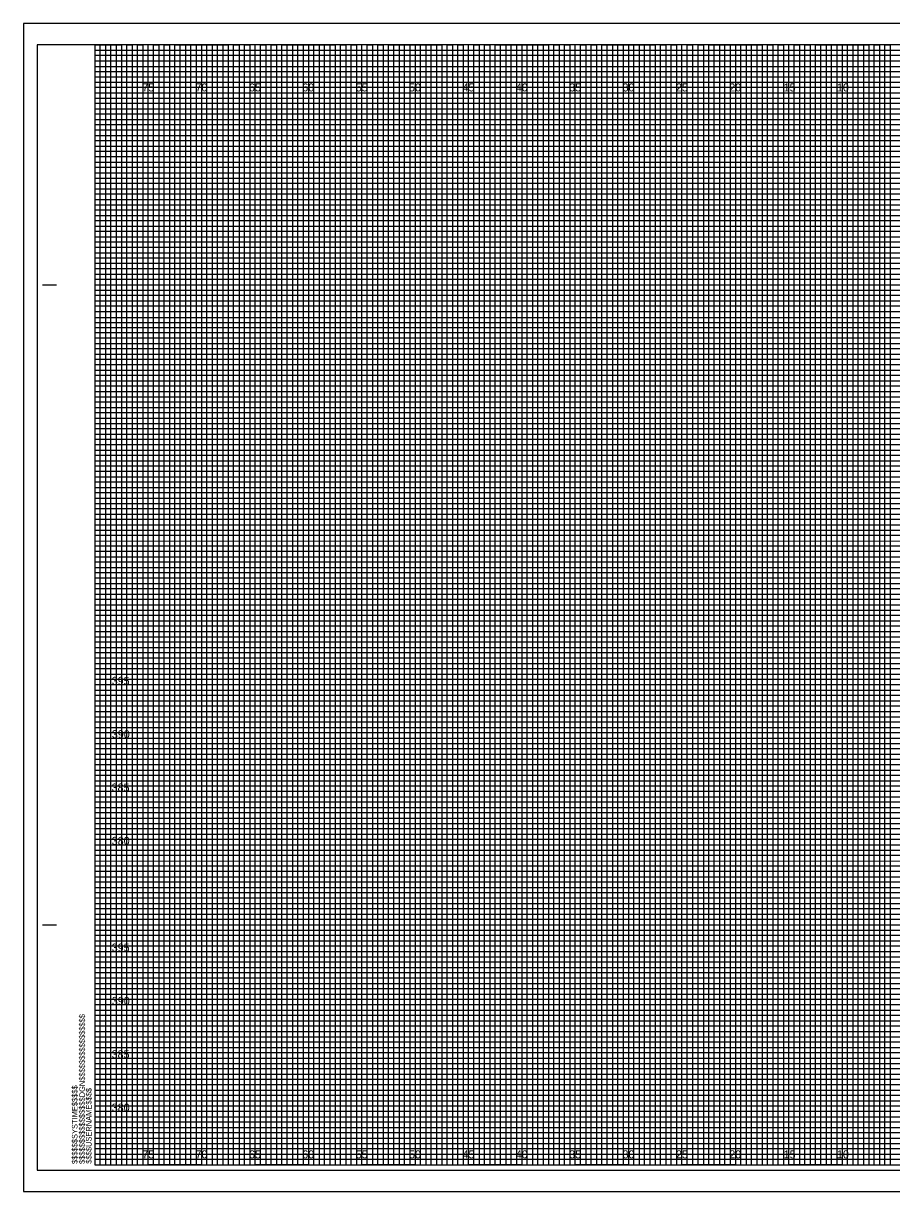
# Model space of a CAD drawing. Extents: x -7 to 162, y -2 to 217.
# Drawn here: x -6.7 to 74.6, y 107.5 to 217 of the extents above; entities that cross this region are included whole.
import ezdxf

# ---------------------------------------------------------------- set-up
doc = ezdxf.new("R2010")
doc.units = 0
for name, color, linetype in [('Exist Cross Section Cell', 7, 'Continuous'), ('Prop CMT Pvmt Course 2', 7, 'Continuous'), ('Prop CMT Pvmt Course 3', 7, 'Continuous'), ('Prop CMT Pvmt Surface Shoulder', 7, 'Continuous'), ('Prop CMT Shld Paved Course 1', 7, 'Continuous'), ('Prop CMT Shld Paved Course 2', 7, 'Continuous'), ('Prop CMT Shld Paved Course 3', 7, 'Continuous'), ('Prop CMT Subgrade Earthwork', 7, 'Continuous'), ('Scratch_Level_3', 7, 'Continuous')]:
    doc.layers.add(name, color=color, linetype=linetype)

msp = doc.modelspace()

# ---------------------------------------------------------------- linework, layer by layer
at = {"layer": 'Prop CMT Pvmt Course 2'}
for p, q in [((0, 214.5), (110.95, 214.5)), ((110.95, 213.99), (0, 213.99)), ((0, 213.99), (0, 213.5)), ((0, 213.5), (110.95, 213.5)), ((110.95, 212.94), (0, 212.94)), ((0, 212.94), (0, 212)), ((0, 212), (160, 212))]:
    msp.add_line(p, q, dxfattribs=at)
for points in [[(0, 211.5), (135, 211.5), (160, 211.5)], [(160, 211), (0, 211)], [(0, 210.5), (160, 210.5)], [(160, 209.5), (0, 209.5)], [(0, 209), (160, 209)], [(160, 208.5), (0, 208.49)], [(0, 208), (160, 208)], [(160, 207), (0, 207)], [(0, 206.5), (160, 206.5), (160, 206), (0, 206)], [(0, 205.5), (160, 205.5), (160, 204.5), (0, 204.5)], [(0, 204), (160, 204), (160, 203.5), (0, 203.5)], [(0, 203), (160, 203), (160, 202), (0, 202)], [(0, 201.5), (160, 201.5), (160, 201), (0, 201)], [(0, 200.5), (160, 200.5), (160, 199.5), (0, 199.5)], [(0, 199), (160, 199), (160, 198.5), (0, 198.5)], [(0, 198), (160, 198), (160, 196.97), (160, 196.5), (160, 196), (0, 196)], [(0, 197), (160, 197), (160, 196.5), (0, 196.5)], [(0, 195.5), (160, 195.5), (160, 194.5), (0, 194.51)], [(0, 194.51), (160, 194.5), (160, 194), (0, 194)], [(0, 193.5), (160, 193.5), (160, 193), (0, 193)], [(0, 192), (160, 192), (160, 191.5), (0, 191.5)], [(0, 191), (160, 191), (160, 190.5), (0, 190.5)], [(-0.04, 189.44), (160, 189.44), (160, 188.94), (-0.04, 188.94)], [(0, 188.5), (160, 188.5), (160, 188), (0, 188)], [(0, 187), (160, 187), (160, 186.5), (0, 186.5)], [(0, 186), (160, 186), (160, 185.5), (0, 185.5)], [(0, 184.5), (160, 184.5), (160, 184), (0, 184)], [(0, 183.5), (160, 183.5), (160, 183), (0, 183)], [(0, 182), (160, 182), (160, 181.5), (0, 181.5)], [(0, 181), (160, 181), (160, 180.5), (0, 180.5)], [(0, 179.5), (160, 179.5), (159.99, 178.99), (0, 179)], [(0, 178.5), (160, 178.5), (160, 178), (0, 178)], [(0, 177), (160, 177), (160, 176.5), (0, 176.5)], [(0, 176), (160, 176), (160, 175.5), (0, 175.5)], [(0, 174.5), (160, 174.5), (160, 174), (0, 174)], [(0, 173.5), (160, 173.5), (160, 173), (0, 173)], [(0, 172), (160, 172), (160, 171.5), (0, 171.5)], [(0, 171), (160, 171), (160, 170.5), (0, 170.5)], [(0, 169.5), (160, 169.5), (160, 169), (0, 169)], [(0, 168.5), (160.03, 168.45), (160, 168), (0, 168)], [(0, 167), (160, 167), (160, 166.5), (0, 166.5)], [(0, 166), (160, 166), (160, 165.5), (0, 165.5)], [(0, 164.5), (160, 164.5), (160, 164), (0, 164)], [(0, 163.5), (160, 163.5), (160, 163), (0, 163)], [(0, 162), (160, 162), (160, 161.5), (0, 161.5)], [(0, 161), (160, 161), (160, 160.5), (0, 160.5)], [(0, 159.5), (160, 159.5), (160, 159), (0, 159)], [(0, 158.5), (160, 158.5), (160, 158), (0, 158)], [(0, 157), (160, 157), (160, 156.5), (0, 156.5)], [(0, 156), (160, 156), (160, 155.5), (0, 155.5)], [(0, 154.5), (160, 154.5), (160, 154), (0, 154)], [(0, 153.5), (160, 153.5), (160, 153), (0, 153)], [(0, 152), (160, 152), (160, 151.5), (0, 151.5)], [(0, 151), (160, 151), (160, 150.5), (0, 150.5)], [(0, 149.5), (160, 149.5), (159.99, 148.99), (0, 149)], [(0, 148.5), (160, 148.5), (160, 148), (0, 148)], [(0, 147), (160, 147), (160, 146.5), (0, 146.5)], [(0, 146), (160, 146), (160, 145.5), (0, 145.5)], [(0, 144.5), (160, 144.5), (160, 144), (0, 144)], [(0, 143.5), (160, 143.5), (160, 143), (0, 143)], [(0, 142), (160, 142), (160, 141.5), (0, 141.5)], [(0, 141), (160, 141), (160, 140.5), (0, 140.5)], [(0, 139.5), (160, 139.5), (160, 139), (0, 139)], [(0, 138.5), (160.03, 138.46), (160, 138), (0, 138)], [(0, 137), (160, 137), (160, 136.5), (0, 136.5)], [(0, 136), (160, 136), (160, 135.5), (0, 135.5)], [(0, 134.5), (160, 134.5), (160, 134), (0, 134)], [(0, 133.5), (160, 133.5), (160, 133), (0, 133)], [(0, 132), (160, 132), (160, 131.5), (0, 131.5)], [(0, 131), (160, 131), (160, 130.5), (0, 130.5)], [(0, 129.5), (160, 129.5), (160, 129), (0, 129)], [(0, 128.5), (160, 128.5), (160, 128), (0, 128)], [(0, 127), (160, 127), (160, 126.5), (0, 126.5)], [(0, 126), (160, 126), (160, 125.5), (0, 125.5)], [(0, 124.5), (160, 124.5), (160, 124), (0, 124)], [(0, 123.5), (160, 123.5), (160, 123), (0, 123)], [(0, 122), (160, 122), (160, 121.5), (0, 121.5)], [(0, 121), (160, 121), (160, 120.5), (0, 120.5)], [(0, 119.5), (160, 119.5), (160, 119), (0, 119)], [(0, 118.5), (160, 118.5), (160, 118), (0, 118)], [(0, 117), (160, 117), (160, 116.5), (0, 116.5)], [(0, 116), (160, 116), (160, 115.5), (0, 115.5)], [(0, 114.5), (160, 114.5), (160, 114), (0, 114)], [(0, 113.5), (160, 113.5), (160, 113), (0, 113)], [(0, 112), (160, 112), (160, 111.5), (0, 111.5)], [(0, 111), (160, 111), (160, 110.5), (0, 110.5)]]:
    msp.add_lwpolyline(points, dxfattribs=at)
at = {"layer": 'Prop CMT Pvmt Course 3'}
for p, q in [((5, 215), (0, 215)), ((5, 110), (5, 215)), ((15, 215), (10, 215)), ((10, 215), (10, 110)), ((15, 110), (15, 215)), ((25, 215), (20, 215)), ((20, 215), (20, 110)), ((25, 110), (25, 215)), ((35, 215), (30, 215)), ((30, 215), (30, 110)), ((35, 110), (35, 215)), ((45, 215), (40, 215)), ((40, 215), (40, 110)), ((45, 110), (45, 215)), ((55, 215), (50, 215)), ((50, 215), (50, 110)), ((55, 110), (55, 215)), ((65, 215), (60, 215)), ((60, 215), (60, 110)), ((65, 110), (65, 215)), ((75, 215), (70, 215)), ((70, 215), (70, 110)), ((10, 110), (5, 110)), ((20, 110), (15, 110)), ((30, 110), (25, 110)), ((40, 110), (35, 110)), ((50, 110), (45, 110)), ((60, 110), (55, 110)), ((70, 110), (65, 110))]:
    msp.add_line(p, q, dxfattribs=at)
for points in [[(160, 212.5), (160, 205), (0, 205)], [(0, 210), (160, 210)], [(0, 200), (160, 200), (160, 195), (0, 195)], [(0, 190), (160, 190), (160, 185), (0, 185)], [(0, 180), (160, 180), (160, 175), (0, 175)], [(0, 170), (160, 170), (160, 165), (0, 165)], [(0, 160), (160, 160), (160, 155), (0, 155)], [(0, 150), (160, 150), (160, 145), (0, 145)], [(0, 140), (160, 140), (160, 135), (0, 135)], [(0, 130), (160, 130), (160, 125), (0, 125)], [(0, 120), (160, 120), (160, 115), (0, 115)]]:
    msp.add_lwpolyline(points, dxfattribs=at)
at = {"layer": 'Prop CMT Shld Paved Course 1'}
msp.add_lwpolyline([(-6.7, 107.5), (161.65, 107.5), (161.65, 217), (-6.7, 217)], close=True, dxfattribs=at)
at = {"layer": 'Prop CMT Shld Paved Course 2'}
msp.add_lwpolyline([(-5.4, 109.5), (161.2, 109.5), (161.2, 215), (-5.4, 215)], close=True, dxfattribs=at)
at = {"layer": 'Prop CMT Shld Paved Course 3'}
for points in [[(0, 215), (2.5, 215), (2.5, 110), (7.5, 110), (7.5, 215), (12.5, 215), (12.5, 110), (17.5, 110), (17.5, 215), (22.5, 215), (22.5, 110), (27.5, 110), (27.5, 215), (32.5, 215), (32.5, 110), (37.5, 110), (37.5, 215), (42.5, 215), (42.5, 110), (47.5, 110), (47.5, 215), (52.5, 215), (52.5, 110), (57.5, 110), (57.5, 215), (62.5, 215), (62.5, 110), (67.5, 110), (67.5, 215), (72.5, 215), (72.5, 110), (77.5, 110)], [(0, 212.5), (137.5, 212.5)], [(0, 202.5), (160, 202.5), (160, 212.5)], [(160, 207.5), (0, 207.5)], [(0, 192.5), (160, 192.5), (160, 197.5), (0, 197.5)], [(0, 182.5), (160, 182.5), (160, 187.5), (0, 187.5)], [(0, 172.5), (160, 172.5), (160, 177.5), (0, 177.5)], [(0, 162.5), (160, 162.5), (160, 167.5), (0, 167.5)], [(0, 152.5), (160, 152.5), (160, 157.5), (0, 157.5)], [(0, 142.5), (160, 142.5), (160, 147.5), (0, 147.5)], [(0, 132.5), (160, 132.5), (160, 137.5), (0, 137.5)], [(0, 122.5), (160, 122.5), (160, 127.5), (0, 127.5)], [(0, 112.5), (160, 112.5), (160, 117.5), (0, 117.5)]]:
    msp.add_lwpolyline(points, dxfattribs=at)
at = {"layer": 'Prop CMT Subgrade Earthwork'}
for points in [[(0, 110), (0.5, 110), (0.5, 215), (1, 215), (1, 110)], [(1, 110), (1.5, 110), (1.5, 215), (2, 215), (2, 110)], [(2.5, 110), (3, 110), (3, 215), (3.5, 215), (3.5, 110)], [(3.5, 110), (4, 110), (4, 215), (4.5, 215), (4.5, 110)], [(5, 110), (5.5, 110), (5.5, 215), (6, 215), (6, 110)], [(6, 110), (6.5, 110), (6.5, 215), (7, 215), (7, 110)], [(7.5, 110), (8, 110), (8, 215), (8.5, 215), (8.5, 110)], [(8.5, 110), (9, 110), (9, 215), (9.5, 215), (9.5, 110)], [(10, 110), (10.5, 110), (10.5, 215), (11, 215), (11, 110)], [(11, 110), (11.5, 110), (11.5, 215), (12, 215), (12, 110)], [(12.5, 110), (13, 110), (13, 215), (13.5, 215), (13.5, 110)], [(13.5, 110), (14, 110), (14, 215), (14.5, 215), (14.5, 110)], [(15, 110), (15.5, 110), (15.5, 215), (16, 215), (16, 110)], [(16, 110), (16.5, 110), (16.5, 215), (17, 215), (17, 110)], [(17.5, 110), (18, 110), (18, 215), (18.5, 215), (18.5, 110)], [(18.5, 110), (19, 110), (19, 215), (19.5, 215), (19.5, 110)], [(20, 110), (20.5, 110), (20.5, 215), (21, 215), (21, 110)], [(21, 110), (21.5, 110), (21.5, 215), (22, 215), (22, 110)], [(22.5, 110), (23, 110), (23, 215), (23.5, 215), (23.5, 110)], [(23.5, 110), (24, 110), (24, 215), (24.5, 215), (24.5, 110)], [(25, 110), (25.5, 110), (25.5, 215), (26, 215), (26, 110)], [(26, 110), (26.5, 110), (26.5, 215), (27, 215), (27, 110)], [(27.5, 110), (28, 110), (28, 215), (28.5, 215), (28.5, 110)], [(28.5, 110), (29, 110), (29, 215), (29.5, 215), (29.5, 110)], [(30, 110), (30.5, 110), (30.5, 215), (31, 215), (31, 110)], [(31, 110), (31.5, 110), (31.5, 215), (32, 215), (32, 110)], [(32.5, 110), (33, 110), (33, 215), (33.5, 215), (33.5, 110)], [(33.5, 110), (34, 110), (34, 215), (34.5, 215), (34.5, 110)], [(35, 110), (35.5, 110), (35.5, 215), (36, 215), (36, 110)], [(36, 110), (36.5, 110), (36.5, 215), (37, 215), (37, 110)], [(37.5, 110), (38, 110), (38, 215), (38.5, 215), (38.5, 110)], [(38.5, 110), (39, 110), (39, 215), (39.5, 215), (39.5, 110)], [(40, 110), (40.5, 110), (40.5, 215), (41, 215), (41, 110)], [(41, 110), (41.5, 110), (41.5, 215), (42, 215), (42, 110)], [(42.5, 110), (43, 110), (43, 215), (43.5, 215), (43.5, 110)], [(43.5, 110), (44, 110), (44, 215), (44.5, 215), (44.5, 110)], [(45, 110), (45.5, 110), (45.5, 215), (46, 215), (46, 110)], [(46, 110), (46.5, 110), (46.5, 215), (47, 215), (47, 110)], [(47.5, 110), (48, 110), (48, 215), (48.5, 215), (48.5, 110)], [(48.5, 110), (49, 110), (49, 215), (49.5, 215), (49.5, 110)], [(50, 110), (50.5, 110), (50.5, 215), (51, 215), (51, 110)], [(51, 110), (51.5, 110), (51.5, 215), (52, 215), (52, 110)], [(52.5, 110), (53, 110), (53, 215), (53.5, 215), (53.5, 110)], [(53.5, 110), (54, 110), (54, 215), (54.5, 215), (54.5, 110)], [(55, 110), (55.5, 110), (55.5, 215), (56, 215), (56, 110)], [(56, 110), (56.5, 110), (56.5, 215), (57, 215), (57, 110)], [(57.5, 110), (58, 110), (58, 215), (58.5, 215), (58.5, 110)], [(58.5, 110), (59, 110), (59, 215), (59.5, 215), (59.5, 110)], [(60, 110), (60.5, 110), (60.5, 215), (61, 215), (61, 110)], [(61, 110), (61.5, 110), (61.5, 215), (62, 215), (62, 110)], [(62.5, 110), (63, 110), (63, 215), (63.5, 215), (63.5, 110)], [(63.5, 110), (64, 110), (64, 215), (64.5, 215), (64.5, 110)], [(65, 110), (65.5, 110), (65.5, 215), (66, 215), (66, 110)], [(66, 110), (66.5, 110), (66.5, 215), (67, 215), (67, 110)], [(67.5, 110), (68, 110), (68, 215), (68.5, 215), (68.5, 110)], [(68.5, 110), (69, 110), (69, 215), (69.5, 215), (69.5, 110)], [(70, 110), (70.5, 110), (70.5, 215), (71, 215), (71, 110)], [(71, 110), (71.5, 110), (71.5, 215), (72, 215), (72, 110)], [(72.5, 110), (73, 110), (73, 215), (73.5, 215), (73.5, 110)], [(73.5, 110), (74, 110), (74, 215), (74.5, 215), (74.5, 110)]]:
    msp.add_lwpolyline(points, dxfattribs=at)
at = {"layer": 'Scratch_Level_3'}
for p, q in [((-4.9, 192.5), (-3.65, 192.5)), ((-4.85, 192.5), (-3.6, 192.5)), ((-4.9, 132.5), (-3.65, 132.5)), ((-4.85, 132.5), (-3.6, 132.5)), ((0, 110), (0, 110)), ((0, 110), (0, 110)), ((0, 110), (0, 110)), ((0, 110), (0, 110)), ((0, 110), (0, 110)), ((0, 110), (0, 110)), ((0, 110), (0, 110))]:
    msp.add_line(p, q, dxfattribs=at)
msp.add_lwpolyline([(160, 215), (0, 215), (0, 110), (160, 110)], close=True, dxfattribs=at)

# ---------------------------------------------------------------- texts
at = {"layer": 'Exist Cross Section Cell'}
for s, p in [('75', (4.44, 210.62)), ('70', (9.43, 210.62)), ('65', (14.44, 210.62)), ('60', (19.43, 210.62)), ('55', (24.44, 210.62)), ('50', (29.43, 210.62)), ('45', (34.44, 210.62)), ('40', (39.43, 210.62)), ('35', (44.44, 210.62)), ('30', (49.43, 210.62)), ('25', (54.44, 210.62)), ('20', (59.43, 210.62)), ('15', (64.53, 210.62)), ('10', (69.52, 210.62)), ('75', (4.44, 110.62)), ('70', (9.43, 110.62)), ('65', (14.44, 110.62)), ('60', (19.43, 110.62)), ('55', (24.44, 110.62)), ('50', (29.43, 110.62)), ('45', (34.44, 110.62)), ('40', (39.43, 110.62)), ('35', (44.44, 110.62)), ('30', (49.43, 110.62)), ('25', (54.44, 110.62)), ('20', (59.43, 110.62)), ('15', (64.53, 110.62)), ('10', (69.52, 110.62))]:
    msp.add_text(s, height=0.75, dxfattribs=at).set_placement(p)
at = {"layer": 'Prop CMT Pvmt Surface Shoulder'}
for s, p in [('395', (1.58, 155)), ('390', (1.59, 150)), ('385', (1.57, 145)), ('380', (1.58, 140)), ('395', (1.58, 130)), ('390', (1.59, 125)), ('385', (1.57, 120)), ('380', (1.58, 115))]:
    msp.add_text(s, height=0.75, dxfattribs=at).set_placement(p)
at = {"layer": 'Scratch_Level_3'}
for s, p in [('$$$$$$$$$$$$$$$$DGN$$$$$$$$$$$$$$$$', (-0.94, 110.09)), ('$$$$$$SYSTIME$$$$$', (-1.63, 110.09)), ('$$$$USERNAME$$$$', (-0.31, 110.12))]:
    msp.add_text(s, height=0.525, rotation=90, dxfattribs=at).set_placement(p)

doc.saveas('drawing.dxf')
